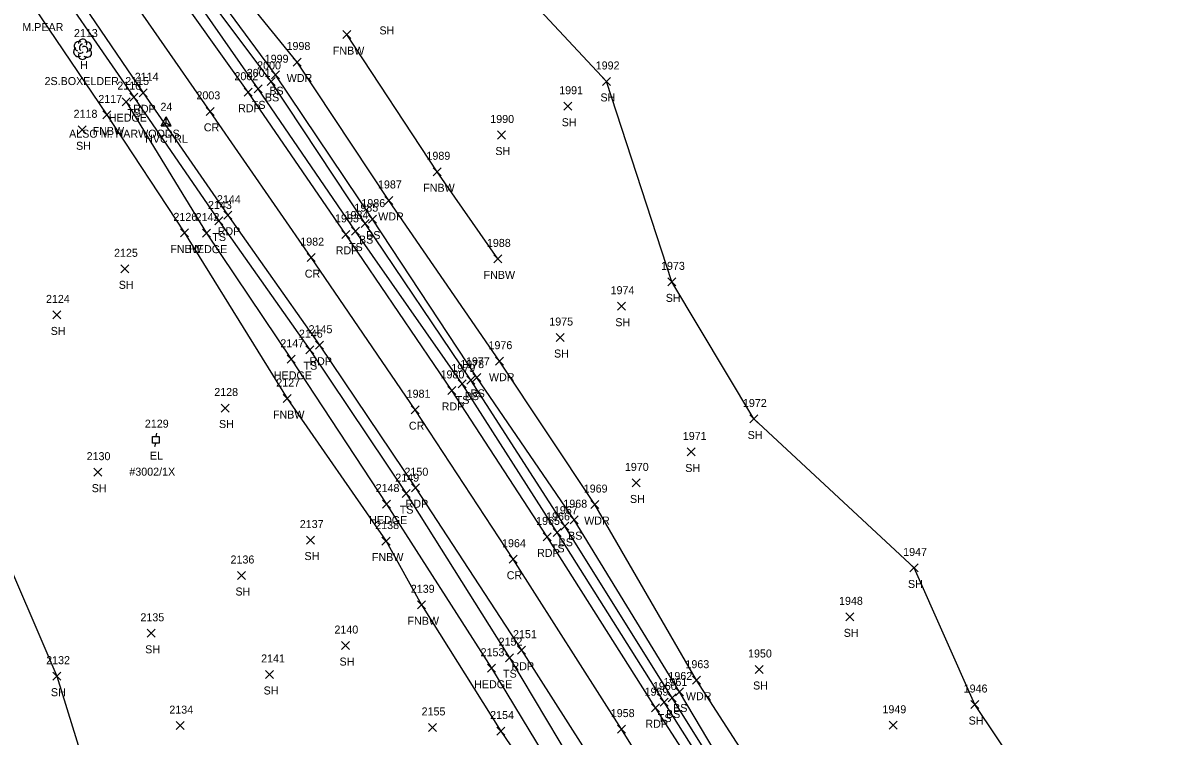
# Model space of a CAD drawing. Extents: x 1443590 to 1445966, y 578314 to 580556.
# Drawn here: x 1444839 to 1445125.4, y 579335.5 to 579513.7 of the extents above; entities that cross this region are included whole.
import ezdxf

# ---------------------------------------------------------------- set-up
doc = ezdxf.new("R2010")
doc.units = 0
for name, color, linetype in [('C_A', 7, 'Continuous'), ('C_I', 7, 'Continuous'), ('CPSM', 7, 'Continuous'), ('L_A', 7, 'Continuous'), ('L_C', 7, 'Continuous'), ('L_I', 7, 'Continuous'), ('L_TIC', 7, 'Continuous'), ('LAHR', 7, 'Continuous'), ('LAWA', 7, 'Continuous'), ('LELB', 7, 'Continuous'), ('LFNC', 7, 'Continuous'), ('LSOGP', 7, 'Continuous'), ('LTD', 7, 'Continuous'), ('P_A', 7, 'Continuous'), ('P_I', 7, 'Continuous'), ('P_TIC', 7, 'Continuous'), ('PET', 7, 'Continuous'), ('PRC', 7, 'Continuous'), ('U_A', 7, 'Continuous'), ('U_C', 7, 'Continuous'), ('U_I', 7, 'Continuous'), ('UEPT', 7, 'Continuous')]:
    doc.layers.add(name, color=color, linetype=linetype)

msp = doc.modelspace()

# ---------------------------------------------------------------- linework, layer by layer
at = {"layer": 'CPSM'}
for p, q in [((1444873.6, 579488.03), (1444874.85, 579490.2)), ((1444876.1, 579488.03), (1444874.85, 579490.2)), ((1444874.85, 579488.75), (1444874.85, 579490.2)), ((1444873.6, 579488.03), (1444874.85, 579488.75)), ((1444873.6, 579488.03), (1444876.1, 579488.03)), ((1444874.85, 579488.75), (1444874.85, 579488.75)), ((1444874.85, 579488.75), (1444876.1, 579488.03))]:
    msp.add_line(p, q, dxfattribs=at)
at = {"layer": 'L_TIC'}
for points in [[(1444918.98, 579509.78), (1444920.98, 579511.78)], [(1444920.98, 579509.78), (1444918.98, 579511.78)], [(1444906.58, 579502.94), (1444908.58, 579504.94)], [(1444908.58, 579502.94), (1444906.58, 579504.94)], [(1444901.15, 579499.76), (1444903.15, 579501.76)], [(1444903.15, 579499.76), (1444901.15, 579501.76)], [(1444896.81, 579496.23), (1444898.81, 579498.23)], [(1444898.81, 579496.23), (1444896.81, 579498.23)], [(1444900.05, 579498.1), (1444902.05, 579500.1)], [(1444902.05, 579498.1), (1444900.05, 579500.1)], [(1444983.83, 579498.09), (1444985.83, 579500.09)], [(1444985.83, 579498.09), (1444983.83, 579500.09)], [(1444865.71, 579494.19), (1444867.71, 579496.19)], [(1444867.71, 579494.19), (1444865.71, 579496.19)], [(1444863.79, 579493.03), (1444865.79, 579495.03)], [(1444865.79, 579493.03), (1444863.79, 579495.03)], [(1444974.14, 579491.89), (1444976.14, 579493.89)], [(1444976.14, 579491.89), (1444974.14, 579493.89)], [(1444858.99, 579489.71), (1444860.99, 579491.71)], [(1444860.99, 579489.71), (1444858.99, 579491.71)], [(1444852.82, 579486), (1444854.82, 579488)], [(1444854.82, 579486), (1444852.82, 579488)], [(1444957.57, 579484.7), (1444959.57, 579486.7)], [(1444959.57, 579484.7), (1444957.57, 579486.7)], [(1444941.56, 579475.51), (1444943.56, 579477.51)], [(1444943.56, 579475.51), (1444941.56, 579477.51)], [(1444929.43, 579468.34), (1444931.43, 579470.34)], [(1444931.43, 579468.34), (1444929.43, 579470.34)], [(1444886.95, 579463.21), (1444888.95, 579465.21)], [(1444888.95, 579463.21), (1444886.95, 579465.21)], [(1444923.55, 579462.55), (1444925.55, 579464.55)], [(1444925.55, 579462.55), (1444923.55, 579464.55)], [(1444925.34, 579463.68), (1444927.34, 579465.68)], [(1444927.34, 579463.68), (1444925.34, 579465.68)], [(1444878.37, 579460.24), (1444880.37, 579462.24)], [(1444880.37, 579460.24), (1444878.37, 579462.24)], [(1444883.87, 579460.17), (1444885.87, 579462.17)], [(1444885.87, 579460.17), (1444883.87, 579462.17)], [(1444921.09, 579460.69), (1444923.09, 579462.69)], [(1444923.09, 579460.69), (1444921.09, 579462.69)], [(1444956.64, 579453.73), (1444958.64, 579455.73)], [(1444958.64, 579453.73), (1444956.64, 579455.73)], [(1444863.5, 579451.25), (1444865.5, 579453.25)], [(1444865.5, 579451.25), (1444863.5, 579453.25)], [(1445000.14, 579447.99), (1445002.14, 579449.99)], [(1445002.14, 579447.99), (1445000.14, 579449.99)], [(1444987.55, 579441.91), (1444989.55, 579443.91)], [(1444989.55, 579441.91), (1444987.55, 579443.91)], [(1444846.48, 579439.73), (1444848.48, 579441.73)], [(1444848.48, 579439.73), (1444846.48, 579441.73)], [(1444972.22, 579434.08), (1444974.22, 579436.08)], [(1444974.22, 579434.08), (1444972.22, 579436.08)], [(1444909.73, 579431.04), (1444911.73, 579433.04)], [(1444911.73, 579431.04), (1444909.73, 579433.04)], [(1444905.03, 579428.64), (1444907.03, 579430.64)], [(1444907.03, 579428.64), (1444905.03, 579430.64)], [(1444957.1, 579428.17), (1444959.1, 579430.17)], [(1444959.1, 579428.17), (1444957.1, 579430.17)], [(1444947.75, 579422.47), (1444949.75, 579424.47)], [(1444949.75, 579422.47), (1444947.75, 579424.47)], [(1444949.97, 579423.44), (1444951.97, 579425.44)], [(1444951.97, 579423.44), (1444949.97, 579425.44)], [(1444951.41, 579424.12), (1444953.41, 579426.12)], [(1444953.41, 579424.12), (1444951.41, 579426.12)], [(1444904.02, 579418.83), (1444906.02, 579420.83)], [(1444906.02, 579418.83), (1444904.02, 579420.83)], [(1444888.52, 579416.46), (1444890.52, 579418.46)], [(1444890.52, 579416.46), (1444888.52, 579418.46)], [(1445020.6, 579413.72), (1445022.6, 579415.72)], [(1445022.6, 579413.72), (1445020.6, 579415.72)], [(1445005.02, 579405.48), (1445007.02, 579407.48)], [(1445007.02, 579405.48), (1445005.02, 579407.48)], [(1444856.73, 579400.43), (1444858.73, 579402.43)], [(1444858.73, 579400.43), (1444856.73, 579402.43)], [(1444991.2, 579397.74), (1444993.2, 579399.74)], [(1444993.2, 579397.74), (1444991.2, 579399.74)], [(1444933.76, 579395.06), (1444935.76, 579397.06)], [(1444935.76, 579395.06), (1444933.76, 579397.06)], [(1444928.84, 579392.46), (1444930.84, 579394.46)], [(1444930.84, 579392.46), (1444928.84, 579394.46)], [(1444980.88, 579392.33), (1444982.88, 579394.33)], [(1444982.88, 579392.33), (1444980.88, 579394.33)], [(1444975.79, 579388.55), (1444977.79, 579390.55)], [(1444977.79, 579388.55), (1444975.79, 579390.55)], [(1444971.54, 579385.39), (1444973.54, 579387.39)], [(1444973.54, 579385.39), (1444971.54, 579387.39)], [(1444973.42, 579386.92), (1444975.42, 579388.92)], [(1444975.42, 579386.92), (1444973.42, 579388.92)], [(1444909.89, 579383.46), (1444911.89, 579385.46)], [(1444911.89, 579383.46), (1444909.89, 579385.46)], [(1444928.74, 579383.21), (1444930.74, 579385.21)], [(1444930.74, 579383.21), (1444928.74, 579385.21)], [(1445060.65, 579376.49), (1445062.65, 579378.49)], [(1445062.65, 579376.49), (1445060.65, 579378.49)], [(1444892.65, 579374.6), (1444894.65, 579376.6)], [(1444894.65, 579374.6), (1444892.65, 579376.6)], [(1444937.64, 579367.28), (1444939.64, 579369.28)], [(1444939.64, 579367.28), (1444937.64, 579369.28)], [(1445044.62, 579364.27), (1445046.62, 579366.27)], [(1445046.62, 579364.27), (1445044.62, 579366.27)], [(1444870.09, 579360.16), (1444872.09, 579362.16)], [(1444872.09, 579360.16), (1444870.09, 579362.16)], [(1444918.64, 579357.09), (1444920.64, 579359.09)], [(1444920.64, 579357.09), (1444918.64, 579359.09)], [(1444959.57, 579354.06), (1444961.57, 579356.06)], [(1444961.57, 579354.06), (1444959.57, 579356.06)], [(1444955.06, 579351.42), (1444957.06, 579353.42)], [(1444957.06, 579351.42), (1444955.06, 579353.42)], [(1445021.97, 579351.11), (1445023.97, 579353.11)], [(1445023.97, 579351.11), (1445021.97, 579353.11)], [(1444846.54, 579349.44), (1444848.54, 579351.44)], [(1444848.54, 579349.44), (1444846.54, 579351.44)], [(1444899.67, 579349.87), (1444901.67, 579351.87)], [(1444901.67, 579349.87), (1444899.67, 579351.87)], [(1445006.29, 579348.44), (1445008.29, 579350.44)], [(1445008.29, 579348.44), (1445006.29, 579350.44)], [(1445002.03, 579345.49), (1445004.03, 579347.49)], [(1445004.03, 579345.49), (1445002.03, 579347.49)], [(1444998.24, 579342.98), (1445000.24, 579344.98)], [(1445000.24, 579342.98), (1444998.24, 579344.98)], [(1445000.25, 579343.99), (1445002.25, 579345.99)], [(1445002.25, 579343.99), (1445000.25, 579345.99)], [(1445075.81, 579342.35), (1445077.81, 579344.35)], [(1445077.81, 579342.35), (1445075.81, 579344.35)], [(1444877.3, 579337.08), (1444879.3, 579339.08)], [(1444879.3, 579337.08), (1444877.3, 579339.08)], [(1444940.32, 579336.63), (1444942.32, 579338.63)], [(1444942.32, 579336.63), (1444940.32, 579338.63)], [(1444957.45, 579335.73), (1444959.45, 579337.73)], [(1444959.45, 579335.73), (1444957.45, 579337.73)], [(1445055.47, 579337.17), (1445057.47, 579339.17)], [(1445057.47, 579337.17), (1445055.47, 579339.17)]]:
    msp.add_lwpolyline(points, dxfattribs=at)
at = {"layer": 'LAHR'}
msp.add_lwpolyline([(1444864.79, 579494.03), (1444884.87, 579461.17), (1444906.03, 579429.64), (1444929.84, 579393.46), (1444956.06, 579352.42), (1444974.79, 579321.64), (1444998.4, 579286.69)], dxfattribs=at)
at = {"layer": 'LAWA'}
msp.add_lwpolyline([(1445116.41, 579282.36), (1445091.57, 579273.6), (1445068.08, 579261.13), (1445063.97, 579265.77), (1445052.44, 579285.91), (1445030.61, 579313.29), (1445007.29, 579349.44), (1444981.88, 579393.33), (1444958.1, 579429.17), (1444930.43, 579469.34), (1444907.58, 579503.94), (1444877.79, 579540.6), (1444853.64, 579577.69), (1444828.42, 579618.05), (1444811.24, 579649.86), (1444793.14, 579680.39), (1444780.3, 579709.09)], dxfattribs=at)
at = {"layer": 'LELB'}
for points in [[(1445120.75, 579274.75), (1445095.98, 579262.15), (1445072.07, 579253.49), (1445056.72, 579252.73), (1445039.69, 579277.16), (1445039.13, 579277.92), (1445021.32, 579309.06), (1444999.24, 579343.98), (1444972.54, 579386.39), (1444948.75, 579423.47), (1444922.09, 579461.69), (1444897.81, 579497.23), (1444870.77, 579536.13), (1444845.96, 579571.78), (1444819.96, 579613.15), (1444802.08, 579645.41), (1444784.76, 579676.08), (1444769.89, 579705.02)], [(1445120.88, 579277.2), (1445094.09, 579267.75), (1445069.76, 579257.75), (1445059.62, 579258.9), (1445056.87, 579257.54), (1445041.61, 579277.38), (1445040.78, 579278.47), (1445023.19, 579309.75), (1445001.25, 579344.99), (1444974.42, 579387.92), (1444950.97, 579424.44), (1444924.55, 579463.55), (1444901.05, 579499.1), (1444872.7, 579536.92), (1444847.2, 579572.49), (1444820.99, 579613.47), (1444802.94, 579645.55), (1444786.24, 579676.71), (1444770.75, 579705.77)], [(1445059.62, 579258.9), (1445043.89, 579279.61), (1445024.59, 579310.38), (1445003.03, 579346.49), (1444976.79, 579389.55), (1444952.41, 579425.12), (1444926.34, 579464.68), (1444902.15, 579500.76), (1444874.51, 579538.34), (1444849.34, 579574.14), (1444822.42, 579614.33), (1444804.62, 579646.57), (1444787.75, 579677.64), (1444772.75, 579706.54)], [(1444746.95, 579691.28), (1444754.81, 579677.63), (1444764.37, 579659.32), (1444774.71, 579638.31), (1444788.05, 579611.23), (1444796.2, 579597.8), (1444819.99, 579563.54), (1444841.2, 579532.22), (1444866.71, 579495.19), (1444887.95, 579464.21), (1444910.73, 579432.04), (1444934.76, 579396.06), (1444960.57, 579355.06), (1444979.05, 579324.01)]]:
    msp.add_lwpolyline(points, dxfattribs=at)
at = {"layer": 'LFNC'}
for points in [[(1444791.16, 579595.89), (1444815.01, 579560.49), (1444832.41, 579534.43), (1444834.53, 579528.45), (1444859.99, 579490.71), (1444879.37, 579461.24), (1444905.02, 579419.83), (1444929.74, 579384.21), (1444938.64, 579368.28), (1444958.45, 579336.73), (1444970.59, 579318.86)], [(1444957.64, 579454.73), (1444942.56, 579476.51), (1444919.98, 579510.78)]]:
    msp.add_lwpolyline(points, dxfattribs=at)
at = {"layer": 'LSOGP'}
for points in [[(1445098.46, 579311.06), (1445076.81, 579343.35), (1445061.65, 579377.48), (1445021.6, 579414.72), (1445001.14, 579448.99), (1444984.82, 579499.09), (1444956.31, 579529.61), (1444915.35, 579561.17), (1444895.24, 579595.5), (1444852.33, 579630.49), (1444836.98, 579665.23)], [(1444832.12, 579386.22), (1444847.54, 579350.44), (1444854.99, 579326.23)]]:
    msp.add_lwpolyline(points, dxfattribs=at)
at = {"layer": 'LTD'}
msp.add_line((1444853.91, 579507.18), (1444853.91, 579507.18), dxfattribs=at)
msp.add_line((1444853.91, 579507.18), (1444853.91, 579507.18), dxfattribs=at)
msp.add_arc((1444853.96, 579508.61), 1.05, 335.5272, 180.9563, dxfattribs=at)
for centre, major_axis, ratio, start_param, end_param in [((1444852.83, 579506.47), (0.58, -1.04), 0.959034, 3.141593, 6.283185), ((1444853.12, 579507.85), (1.21, -0.51), 0.895232, 1.570796, 4.712389), ((1444853.45, 579506.43), (-0.625, -0.083), 0.423636, 0, 3.141593), ((1444853.7, 579507.64), (-0.208, -0.792), 0.645439, 3.141593, 6.283185), ((1444854.41, 579507.01), (-0.5, 0.667), 0.989748, 3.141593, 6.283185), ((1444854.91, 579506.35), (-1.09, 0.79), 0.841452, 1.570796, 4.712389), ((1444854.95, 579507.76), (-1.14, -0.48), 0.949671, 1.570796, 4.712389), ((1444853.91, 579505.68), (0.26, 1.06), 0.942809, 1.570796, 4.712389)]:
    msp.add_ellipse(centre, major_axis=major_axis, ratio=ratio, start_param=start_param, end_param=end_param, dxfattribs=at)
at = {"layer": 'P_TIC'}
for points in [[(1444868.08, 579495.25), (1444870.08, 579497.25)], [(1444870.08, 579495.25), (1444868.08, 579497.25)], [(1444894.29, 579495.39), (1444896.29, 579497.39)], [(1444896.29, 579495.39), (1444894.29, 579497.39)], [(1444884.8, 579490.61), (1444886.8, 579492.61)], [(1444886.8, 579490.61), (1444884.8, 579492.61)], [(1444889.19, 579464.65), (1444891.19, 579466.65)], [(1444891.19, 579464.65), (1444889.19, 579466.65)], [(1444918.7, 579459.87), (1444920.7, 579461.87)], [(1444920.7, 579459.87), (1444918.7, 579461.87)], [(1444910.02, 579454.05), (1444912.02, 579456.05)], [(1444912.02, 579454.05), (1444910.02, 579456.05)], [(1444912.09, 579432.16), (1444914.09, 579434.16)], [(1444914.09, 579432.16), (1444912.09, 579434.16)], [(1444945.15, 579420.86), (1444947.15, 579422.86)], [(1444947.15, 579420.86), (1444945.15, 579422.86)], [(1444936.03, 579416.04), (1444938.03, 579418.04)], [(1444938.03, 579416.04), (1444936.03, 579418.04)], [(1444936.14, 579396.54), (1444938.14, 579398.54)], [(1444938.14, 579396.54), (1444936.14, 579398.54)], [(1444968.98, 579384.25), (1444970.98, 579386.25)], [(1444970.98, 579384.25), (1444968.98, 579386.25)], [(1444960.47, 579378.67), (1444962.47, 579380.67)], [(1444962.47, 579378.67), (1444960.47, 579380.67)], [(1444962.6, 579355.94), (1444964.6, 579357.94)], [(1444964.6, 579355.94), (1444962.6, 579357.94)], [(1444996.05, 579341.56), (1444998.05, 579343.56)], [(1444998.05, 579341.56), (1444996.05, 579343.56)], [(1444987.59, 579336.21), (1444989.59, 579338.21)], [(1444989.59, 579336.21), (1444987.59, 579338.21)]]:
    msp.add_lwpolyline(points, dxfattribs=at)
at = {"layer": 'PET'}
for points in [[(1445187.64, 579104.95), (1445149.35, 579115.57), (1445134.36, 579130.22), (1445115.96, 579155.83), (1445098.76, 579182.02), (1445071.93, 579223.13), (1445057.22, 579245.8), (1445037.84, 579275.94), (1445019.3, 579308.07), (1444997.05, 579342.56), (1444969.98, 579385.25), (1444946.15, 579421.86), (1444919.7, 579460.87), (1444895.29, 579496.39), (1444868.39, 579534.19), (1444844.21, 579570.94), (1444818.42, 579612.05), (1444800.46, 579644.42), (1444783.19, 579675.42), (1444768.08, 579703.75)], [(1444749.57, 579692.99), (1444767.18, 579659.68), (1444778.42, 579640.07), (1444792.21, 579615.83), (1444803.11, 579597.28), (1444822.86, 579565.6), (1444843.8, 579533.42), (1444869.08, 579496.25), (1444890.19, 579465.65), (1444913.09, 579433.16), (1444937.14, 579397.54), (1444963.6, 579356.94), (1444983.04, 579326.35), (1445006.82, 579289.13), (1445021.79, 579264.22), (1445044.58, 579229.01), (1445059.66, 579205.24), (1445081.95, 579172.07), (1445091.01, 579154.93), (1445104.63, 579132.07), (1445107.77, 579117.84), (1445102.26, 579109.52), (1445094.76, 579101.93)]]:
    msp.add_lwpolyline(points, dxfattribs=at)
at = {"layer": 'PRC'}
msp.add_lwpolyline([(1445134.69, 579101.81), (1445120.96, 579124.75), (1445105.7, 579149.31), (1445088.61, 579176.47), (1445062.61, 579215.94), (1445046.37, 579243.3), (1445028.61, 579272.2), (1445009.91, 579303.07), (1444988.59, 579337.21), (1444961.47, 579379.67), (1444937.03, 579417.04), (1444911.02, 579455.05), (1444885.8, 579491.61), (1444860.37, 579528.28), (1444835.41, 579566.04), (1444809.93, 579606.59), (1444790.8, 579639.57), (1444773.48, 579670.26), (1444758.9, 579698.36)], dxfattribs=at)
at = {"layer": 'UEPT'}
for p, q in [((1444871.37, 579408.71), (1444871.37, 579410.38)), ((1444871.37, 579410.38), (1444873.03, 579410.38)), ((1444872.37, 579411.21), (1444872.2, 579410.38)), ((1444872.2, 579409.55), (1444872.2, 579409.55)), ((1444873.03, 579410.38), (1444873.03, 579408.71)), ((1444873.03, 579408.71), (1444871.37, 579408.71)), ((1444871.95, 579407.88), (1444872.2, 579408.71))]:
    msp.add_line(p, q, dxfattribs=at)

# ---------------------------------------------------------------- texts
at = {"layer": 'C_A'}
msp.add_text('HVCTRL', height=2, dxfattribs=at).set_placement((1444869.55, 579483.75))
at = {"layer": 'C_I'}
msp.add_text('24', height=2, dxfattribs=at).set_placement((1444873.39, 579491.75))
at = {"layer": 'L_A'}
for s, p in [('SH', (1444928.11, 579510.84)), ('FNBW', (1444916.45, 579505.78)), ('H', (1444853.34, 579502.18)), ('WDR', (1444904.94, 579498.94)), ('BS', (1444899.49, 579494.1)), ('BS', (1444900.59, 579495.76)), ('SH', (1444983.32, 579494.09)), ('TS', (1444865.12, 579490.19)), ('TS', (1444896.22, 579492.23)), ('HEDGE', (1444860.49, 579489.03)), ('SH', (1444973.63, 579487.89)), ('FNBW', (1444856.46, 579485.71)), ('SH', (1444852.31, 579482)), ('SH', (1444957.06, 579480.7)), ('FNBW', (1444939.03, 579471.51)), ('WDR', (1444927.79, 579464.34)), ('TS', (1444886.36, 579459.21)), ('BS', (1444924.78, 579459.68)), ('FNBW', (1444875.85, 579456.24)), ('HEDGE', (1444880.57, 579456.17)), ('TS', (1444920.5, 579456.69)), ('BS', (1444922.99, 579458.55)), ('SH', (1444862.98, 579447.25)), ('FNBW', (1444954.11, 579449.73)), ('SH', (1444999.63, 579443.99)), ('SH', (1444987.03, 579437.91)), ('SH', (1444845.97, 579435.73)), ('SH', (1444971.71, 579430.08)), ('HEDGE', (1444901.73, 579424.64)), ('TS', (1444909.14, 579427.04)), ('WDR', (1444955.46, 579424.17)), ('BS', (1444949.41, 579419.44)), ('BS', (1444950.85, 579420.12)), ('TS', (1444947.16, 579418.47)), ('FNBW', (1444901.5, 579414.83)), ('SH', (1444888.01, 579412.46)), ('SH', (1445020.09, 579409.72)), ('SH', (1445004.51, 579401.48)), ('SH', (1444856.22, 579396.43)), ('SH', (1444990.69, 579393.74)), ('TS', (1444933.17, 579391.06)), ('HEDGE', (1444925.54, 579388.46)), ('WDR', (1444979.25, 579388.33)), ('BS', (1444975.23, 579384.55)), ('TS', (1444970.95, 579381.39)), ('BS', (1444972.86, 579382.92)), ('SH', (1444909.38, 579379.46)), ('FNBW', (1444926.22, 579379.21)), ('SH', (1444892.13, 579370.6)), ('SH', (1445060.14, 579372.49)), ('FNBW', (1444935.11, 579363.28)), ('SH', (1445044.1, 579360.27)), ('SH', (1444869.58, 579356.16)), ('SH', (1444918.13, 579353.09)), ('TS', (1444958.98, 579350.06)), ('HEDGE', (1444951.76, 579347.42)), ('SH', (1445021.45, 579347.11)), ('SH', (1444846.02, 579345.44)), ('SH', (1444899.16, 579345.87)), ('WDR', (1445004.66, 579344.44)), ('BS', (1445001.47, 579341.49)), ('TS', (1444997.65, 579338.98)), ('BS', (1444999.69, 579339.99)), ('SH', (1445075.3, 579338.35))]:
    msp.add_text(s, height=2, dxfattribs=at).set_placement(p)
at = {"layer": 'L_C'}
for s, p in [('M.PEAR', (1444838.88, 579511.68)), ('2S.BOXELDER', (1444844.44, 579498.18)), ('ALSO M. HARWOODS', (1444850.57, 579485.03))]:
    msp.add_text(s, height=2, dxfattribs=at).set_placement(p)
at = {"layer": 'L_I'}
for s, p in [('2113', (1444851.78, 579510.18)), ('1998', (1444904.89, 579506.94)), ('2000', (1444897.55, 579502.1)), ('1999', (1444899.44, 579503.76)), ('1992', (1444982.13, 579502.09)), ('2001', (1444894.96, 579500.23)), ('2116', (1444862.61, 579497.03)), ('2115', (1444864.59, 579498.19)), ('1991', (1444973.01, 579495.89)), ('2117', (1444857.86, 579493.71)), ('2118', (1444851.69, 579490)), ('1990', (1444955.79, 579488.7)), ('1989', (1444939.85, 579479.51)), ('1987', (1444927.74, 579472.34)), ('1986', (1444923.59, 579467.68)), ('2143', (1444885.26, 579467.21)), ('1984', (1444919.4, 579464.69)), ('1985', (1444921.85, 579466.55)), ('2126', (1444876.63, 579464.24)), ('2142', (1444882.18, 579464.17)), ('1988', (1444954.95, 579457.73)), ('2125', (1444861.8, 579455.25)), ('1973', (1444998.45, 579451.99)), ('1974', (1444985.85, 579445.91)), ('2124', (1444844.79, 579443.73)), ('1975', (1444970.53, 579438.08)), ('2146', (1444907.98, 579435.04)), ('2147', (1444903.34, 579432.64)), ('1976', (1444955.35, 579432.17)), ('1978', (1444948.28, 579427.44)), ('1977', (1444949.71, 579428.12)), ('1979', (1444946.05, 579426.47)), ('2127', (1444902.33, 579422.83)), ('2128', (1444886.83, 579420.46)), ('1972', (1445018.91, 579417.72)), ('1971', (1445003.89, 579409.48)), ('2130', (1444854.95, 579404.43)), ('1970', (1444989.42, 579401.74)), ('2149', (1444932.06, 579399.06)), ('2148', (1444927.15, 579396.46)), ('1969', (1444979.14, 579396.33)), ('1967', (1444971.68, 579390.92)), ('1968', (1444974.05, 579392.55)), ('2137', (1444908.2, 579387.46)), ('2138', (1444927.05, 579387.21)), ('1966', (1444969.74, 579389.39)), ('2136', (1444890.9, 579378.6)), ('1947', (1445058.95, 579380.49)), ('2139', (1444935.94, 579371.28)), ('1948', (1445042.92, 579368.27)), ('2135', (1444868.39, 579364.16)), ('2140', (1444916.86, 579361.09)), ('2152', (1444957.87, 579358.06)), ('2132', (1444844.84, 579353.44)), ('2141', (1444898.55, 579353.87)), ('2153', (1444953.37, 579355.42)), ('1950', (1445020.19, 579355.11)), ('1963', (1445004.55, 579352.44)), ('1961', (1444999.07, 579347.99)), ('1962', (1445000.29, 579349.49)), ('1960', (1444996.41, 579346.98)), ('1946', (1445074.06, 579346.35)), ('2134', (1444875.61, 579341.08)), ('2155', (1444938.63, 579340.63)), ('2154', (1444955.76, 579339.73)), ('1949', (1445053.77, 579341.17))]:
    msp.add_text(s, height=2, dxfattribs=at).set_placement(p)
at = {"layer": 'P_A'}
for s, p in [('RDP', (1444866.57, 579491.25)), ('RDP', (1444892.78, 579491.39)), ('CR', (1444884.23, 579486.61)), ('RDP', (1444887.68, 579460.65)), ('RDP', (1444917.18, 579455.87)), ('CR', (1444909.45, 579450.05)), ('RDP', (1444910.58, 579428.16)), ('RDP', (1444943.64, 579416.86)), ('CR', (1444935.46, 579412.04)), ('RDP', (1444934.63, 579392.54)), ('RDP', (1444967.47, 579380.25)), ('CR', (1444959.91, 579374.67)), ('RDP', (1444961.09, 579351.94)), ('RDP', (1444994.53, 579337.56))]:
    msp.add_text(s, height=2, dxfattribs=at).set_placement(p)
at = {"layer": 'P_I'}
for s, p in [('2114', (1444866.96, 579499.25)), ('2002', (1444891.88, 579499.39)), ('2003', (1444882.38, 579494.61)), ('2144', (1444887.5, 579468.65)), ('1983', (1444917, 579463.87)), ('1982', (1444908.32, 579458.05)), ('2145', (1444910.4, 579436.16)), ('1980', (1444943.37, 579424.86)), ('1981', (1444934.9, 579420.04)), ('2150', (1444934.36, 579400.54)), ('1965', (1444967.24, 579388.25)), ('1964', (1444958.73, 579382.67)), ('2151', (1444961.47, 579359.94)), ('1959', (1444994.35, 579345.56)), ('1958', (1444985.9, 579340.21))]:
    msp.add_text(s, height=2, dxfattribs=at).set_placement(p)
at = {"layer": 'U_A'}
msp.add_text('EL', height=2, dxfattribs=at).set_placement((1444870.74, 579404.55))
at = {"layer": 'U_C'}
msp.add_text('#3002/1X', height=2, dxfattribs=at).set_placement((1444865.62, 579400.55))
at = {"layer": 'U_I'}
msp.add_text('2129', height=2, dxfattribs=at).set_placement((1444869.5, 579412.55))

doc.saveas('drawing.dxf')
